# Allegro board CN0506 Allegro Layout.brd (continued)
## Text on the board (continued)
User.15: CHARACTERISTIC IMPEDANCE = 50 OHMS +/- 10% | ARTWORK LINE WIDTH FOR | IMPEDANCE CONTROLLED LINES = .008" | 50 OHMS SE | 100 OHMS DP
User.17: L2 GND | 08-      -07
User.18: L3 SIG | 08-      -08
User.19: L4 GND | 08-      -09
User.20: L5 PWR | 08-      -10
User.23: L6 SIG | 08-      -11
User.24: L7 GND | 08-      -12
User.45: FIGURE | SIZE | 10.0 | 35.0 | 40.0 | 43.0 | 45.0 | 65.0 | 50.0 | 105.0 | 130.0 | PLATED | NON-PLATED | FINISHED HOLES IN MILS | ALL UNITS ARE IN MILS | QTY | 582 | 20 | 8 | 5 | 16 | 4 | 2 | TOLERANCE/NOTES
